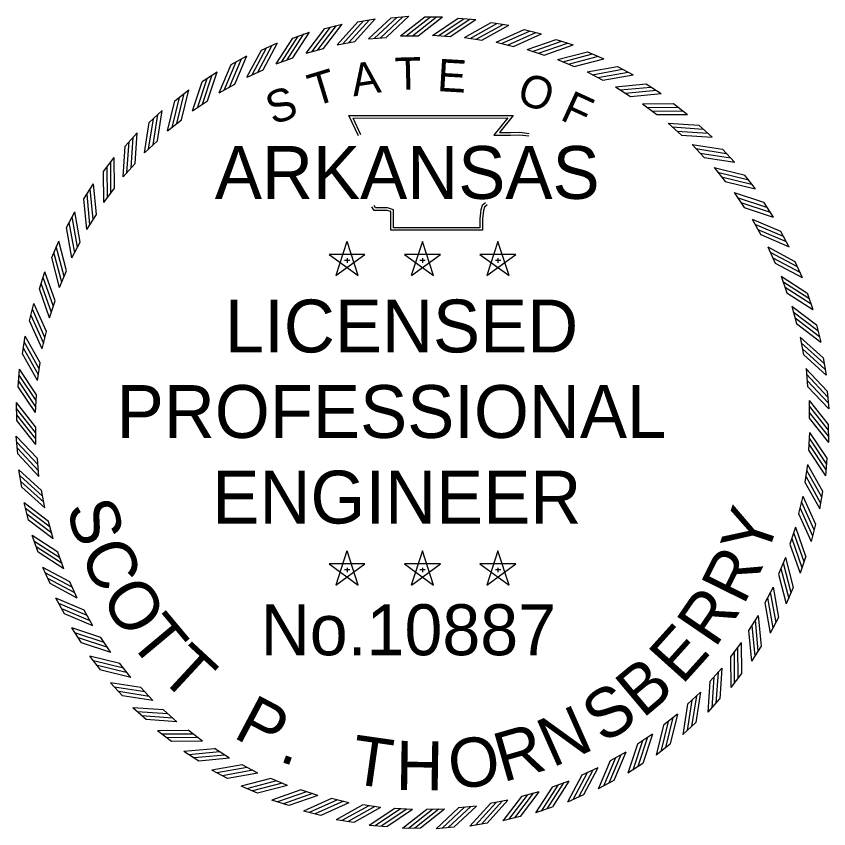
# Model space of a CAD drawing. Extents: x -24122 to 24238, y -8840 to 11381.
# Drawn here: x 3046.5 to 3294.9, y 323.2 to 571.6 of the extents above; entities that cross this region are included whole.
import ezdxf

# ---------------------------------------------------------------- set-up
doc = ezdxf.new("R2010")
doc.units = 0
doc.layers.add('STAMP_PP', color=7, linetype='Continuous')

msp = doc.modelspace()

# ---------------------------------------------------------------- linework, layer by layer
at = {"layer": 'STAMP_PP'}
for p, q in [((3161.08, 571.13), (3166.5, 571.63)), ((3171.39, 571.43), (3176.83, 571.43)), ((3140.85, 567.86), (3146.11, 569.24)), ((3150.9, 569.91), (3156.26, 570.86)), ((3181.58, 571.02), (3187, 570.63)), ((3191.75, 569.7), (3197.12, 568.86)), ((3131.01, 564.98), (3136.14, 566.8)), ((3201.77, 567.55), (3207.06, 566.26)), ((3154.22, 564.68), (3159.65, 565.18)), ((3163.96, 565.64), (3169.41, 565.64)), ((3173.75, 565.8), (3179.19, 565.4)), ((3183.51, 565.14), (3188.9, 564.29)), ((3211.59, 564.57), (3216.75, 562.85)), ((3121.43, 561.3), (3126.4, 563.53)), ((3135.14, 560.37), (3140.42, 561.76)), ((3144.59, 562.92), (3149.96, 563.87)), ((3193.19, 563.68), (3198.49, 562.39)), ((3112.2, 556.85), (3116.96, 559.48)), ((3202.71, 561.42), (3207.89, 559.7)), ((3221.12, 560.8), (3226.13, 558.66)), ((3125.94, 557.05), (3131.08, 558.87)), ((3212.02, 558.39), (3217.03, 556.25)), ((3103.36, 551.64), (3107.89, 554.66)), ((3117.04, 552.98), (3122.01, 555.21)), ((3221.04, 554.6), (3225.86, 552.05)), ((3230.31, 556.24), (3235.12, 553.7)), ((3094.98, 545.72), (3099.24, 549.11)), ((3108.5, 548.19), (3113.27, 550.83)), ((3229.72, 550.08), (3234.32, 547.14)), ((3239.1, 550.95), (3243.68, 548.02)), ((3100.39, 542.71), (3104.93, 545.73)), ((3238, 544.85), (3242.33, 541.54)), ((3247.41, 544.95), (3251.74, 541.64)), ((3087.12, 539.14), (3091.09, 542.86)), ((3092.76, 536.57), (3097.04, 539.96)), ((3245.82, 538.96), (3249.86, 535.3)), ((3255.21, 538.28), (3259.24, 534.63)), ((3079.83, 531.92), (3083.48, 535.96)), ((3085.67, 529.83), (3089.64, 533.56)), ((3253.12, 532.45), (3256.85, 528.47)), ((3262.42, 530.99), (3266.14, 527.02)), ((3073.17, 524.13), (3076.47, 528.45)), ((3079.15, 522.53), (3082.81, 526.58)), ((3259.86, 525.35), (3263.25, 521.08)), ((3269.01, 523.13), (3272.39, 518.87)), ((3067.16, 515.81), (3070.1, 520.39)), ((3073.26, 514.71), (3076.57, 519.05)), ((3265.99, 517.72), (3269.02, 513.18)), ((3274.93, 514.75), (3277.94, 510.23)), ((3061.87, 507.03), (3064.41, 511.84)), ((3068.04, 506.44), (3070.98, 511.03)), ((3271.47, 509.61), (3274.11, 504.84)), ((3280.13, 505.92), (3282.76, 501.15)), ((3057.32, 497.84), (3059.46, 502.84)), ((3063.51, 497.76), (3066.06, 502.58)), ((3147.61, 502.79), (3144.21, 492.34)), ((3151, 492.35), (3147.62, 502.8)), ((3170.69, 502.79), (3167.28, 492.34)), ((3174.08, 492.35), (3170.7, 502.8)), ((3193.77, 502.79), (3190.36, 492.34)), ((3197.16, 492.35), (3193.77, 502.8)), ((3276.26, 501.08), (3278.5, 496.1)), ((3153.1, 498.8), (3142.11, 498.81)), ((3142.12, 498.8), (3151, 492.33)), ((3144.22, 492.35), (3153.11, 498.8)), ((3146.83, 497.04), (3148.46, 497.04)), ((3147.62, 497.63), (3147.62, 496.25)), ((3176.18, 498.8), (3165.19, 498.81)), ((3165.2, 498.8), (3174.08, 492.33)), ((3167.3, 492.35), (3176.19, 498.8)), ((3169.91, 497.04), (3171.54, 497.04)), ((3170.7, 497.63), (3170.7, 496.25)), ((3199.25, 498.8), (3188.27, 498.81)), ((3188.28, 498.8), (3197.16, 492.33)), ((3190.37, 492.35), (3199.27, 498.8)), ((3192.98, 497.04), (3194.62, 497.04)), ((3193.78, 497.63), (3193.78, 496.25)), ((3284.59, 496.68), (3286.82, 491.72)), ((3053.54, 488.3), (3055.26, 493.47)), ((3059.72, 488.74), (3061.86, 493.75)), ((3280.33, 492.18), (3282.15, 487.03)), ((3288.27, 487.11), (3290.08, 481.98)), ((3056.69, 479.43), (3058.41, 484.6)), ((3050.56, 478.49), (3051.85, 483.78)), ((3283.66, 482.97), (3285.04, 477.69)), ((3291.14, 477.26), (3292.53, 472)), ((3054.43, 469.91), (3055.72, 475.2)), ((3048.41, 468.46), (3049.25, 473.84)), ((3286.21, 473.52), (3287.15, 468.15)), ((3293.2, 467.21), (3294.14, 461.86)), ((3052.97, 460.23), (3053.82, 465.61)), ((3047.09, 458.29), (3047.49, 463.72)), ((3287.97, 463.89), (3288.47, 458.46)), ((3052.32, 450.46), (3052.72, 455.9)), ((3294.41, 457.03), (3294.91, 451.61)), ((3046.61, 448.05), (3046.56, 453.49)), ((3288.93, 454.15), (3288.98, 448.7)), ((3052.47, 440.68), (3052.42, 446.13)), ((3294.79, 446.78), (3294.84, 441.34)), ((3046.98, 437.8), (3046.48, 443.22)), ((3289.08, 444.37), (3288.68, 438.93)), ((3053.43, 430.94), (3052.93, 436.37)), ((3294.31, 436.54), (3293.91, 431.11)), ((3048.2, 427.61), (3047.25, 432.97)), ((3288.42, 434.6), (3287.58, 429.21)), ((3055.19, 421.31), (3054.24, 426.68)), ((3286.96, 424.92), (3285.67, 419.62)), ((3292.99, 426.36), (3292.14, 420.99)), ((3050.25, 417.57), (3048.87, 422.83)), ((3057.74, 411.86), (3056.35, 417.13)), ((3284.71, 415.4), (3282.99, 410.22)), ((3290.83, 416.34), (3289.55, 411.05)), ((3053.13, 407.72), (3051.32, 412.85)), ((3061.06, 402.65), (3059.24, 407.79)), ((3147.61, 408.16), (3144.21, 397.72)), ((3151, 397.72), (3147.62, 408.17)), ((3170.69, 408.16), (3167.28, 397.72)), ((3174.08, 397.72), (3170.7, 408.17)), ((3193.77, 408.16), (3190.36, 397.72)), ((3197.16, 397.72), (3193.77, 408.17)), ((3281.68, 406.09), (3279.53, 401.08)), ((3287.86, 406.52), (3286.14, 401.36)), ((3056.81, 398.15), (3054.58, 403.11)), ((3153.1, 404.17), (3142.11, 404.19)), ((3142.12, 404.17), (3151, 397.71)), ((3144.22, 397.72), (3153.11, 404.17)), ((3147.62, 403.01), (3147.62, 401.63)), ((3176.18, 404.17), (3165.19, 404.19)), ((3165.2, 404.17), (3174.08, 397.71)), ((3167.3, 397.72), (3176.19, 404.17)), ((3170.7, 403.01), (3170.7, 401.63)), ((3199.25, 404.17), (3188.27, 404.19)), ((3188.28, 404.17), (3197.16, 397.71)), ((3190.37, 397.72), (3199.27, 404.17)), ((3193.78, 403.01), (3193.78, 401.63)), ((3146.83, 402.42), (3148.46, 402.42)), ((3169.91, 402.42), (3171.54, 402.42)), ((3192.98, 402.42), (3194.62, 402.42)), ((3065.13, 393.75), (3062.9, 398.72)), ((3277.89, 397.07), (3275.33, 392.25)), ((3284.08, 396.99), (3281.94, 391.99)), ((3061.27, 388.91), (3058.63, 393.67)), ((3069.93, 385.22), (3067.29, 389.99)), ((3273.36, 388.39), (3270.42, 383.8)), ((3279.53, 387.8), (3276.98, 382.99)), ((3066.47, 380.07), (3063.45, 384.6)), ((3075.41, 377.11), (3072.38, 381.65)), ((3268.14, 380.11), (3264.83, 375.78)), ((3274.23, 379.01), (3271.3, 374.43)), ((3072.39, 371.7), (3069.01, 375.96)), ((3081.54, 369.48), (3078.15, 373.75)), ((3262.25, 372.3), (3258.59, 368.25)), ((3268.23, 370.7), (3264.93, 366.37)), ((3078.98, 363.84), (3075.25, 367.81)), ((3088.28, 362.38), (3084.55, 366.36)), ((3255.73, 364.99), (3251.75, 361.26)), ((3261.56, 362.91), (3257.92, 358.87)), ((3086.19, 356.55), (3082.15, 360.2)), ((3095.58, 355.87), (3091.54, 359.52)), ((3248.63, 358.25), (3244.36, 354.86)), ((3254.27, 355.69), (3250.31, 351.97)), ((3093.98, 349.88), (3089.66, 353.18)), ((3103.4, 349.98), (3099.06, 353.29)), ((3241, 352.12), (3236.47, 349.1)), ((3246.41, 349.1), (3242.15, 345.72)), ((3102.3, 343.88), (3097.72, 346.81)), ((3111.67, 344.75), (3107.08, 347.69)), ((3232.9, 346.64), (3228.12, 344)), ((3238.04, 343.19), (3233.51, 340.17)), ((3111.08, 338.58), (3106.27, 341.13)), ((3120.35, 340.23), (3115.53, 342.78)), ((3224.36, 341.85), (3219.39, 339.61)), ((3129.38, 336.44), (3124.36, 338.58)), ((3229.2, 337.98), (3224.44, 335.35)), ((3120.27, 334.03), (3115.27, 336.17)), ((3215.46, 337.78), (3210.32, 335.96)), ((3138.68, 333.4), (3133.51, 335.13)), ((3206.25, 334.46), (3200.98, 333.07)), ((3219.96, 333.52), (3215, 331.29)), ((3129.81, 330.26), (3124.65, 331.97)), ((3148.21, 331.15), (3142.91, 332.44)), ((3157.88, 329.69), (3152.5, 330.54)), ((3196.8, 331.91), (3191.43, 330.96)), ((3139.62, 327.28), (3134.34, 328.57)), ((3167.65, 329.03), (3162.21, 329.43)), ((3177.44, 329.18), (3171.98, 329.13)), ((3187.18, 330.14), (3181.75, 329.64)), ((3210.39, 329.84), (3205.26, 328.03)), ((3149.65, 325.12), (3144.28, 325.97)), ((3200.55, 326.97), (3195.28, 325.58)), ((3159.82, 323.8), (3154.39, 324.2)), ((3170.07, 323.33), (3164.62, 323.28)), ((3180.31, 323.7), (3174.9, 323.2)), ((3190.5, 324.91), (3185.14, 323.97))]:
    msp.add_line(p, q, dxfattribs=at)
for points in [[(3157.84, 565.04), (3164.7, 571.48)], [(3159.64, 565.19), (3166.5, 571.63)], [(3163.95, 565.64), (3171.38, 571.43)], [(3165.71, 565.62), (3173.13, 571.41)], [(3167.6, 565.66), (3175.02, 571.45)], [(3169.41, 565.65), (3176.83, 571.44)], [(3140.41, 561.76), (3146.12, 569.25)], [(3144.59, 562.92), (3150.89, 569.91)], [(3146.31, 563.2), (3152.62, 570.19)], [(3148.17, 563.57), (3154.47, 570.56)], [(3149.96, 563.87), (3156.26, 570.86)], [(3154.21, 564.68), (3161.08, 571.12)], [(3155.96, 564.82), (3162.82, 571.27)], [(3173.74, 565.79), (3181.57, 571.02)], [(3175.49, 565.65), (3183.31, 570.88)], [(3177.37, 565.55), (3185.2, 570.78)], [(3179.18, 565.4), (3187.01, 570.63)], [(3183.51, 565.14), (3191.74, 569.7)], [(3185.23, 564.85), (3193.47, 569.41)], [(3187.11, 564.59), (3195.34, 569.16)], [(3131.07, 558.87), (3136.14, 566.8)], [(3135.14, 560.36), (3140.84, 567.85)], [(3136.84, 560.79), (3142.54, 568.28)], [(3138.65, 561.32), (3144.36, 568.8)], [(3188.89, 564.3), (3197.13, 568.86)], [(3193.18, 563.68), (3201.77, 567.55)], [(3194.88, 563.25), (3203.46, 567.12)], [(3196.73, 562.84), (3205.31, 566.71)], [(3125.93, 557.04), (3131, 564.98)], [(3127.59, 557.61), (3132.66, 565.54)], [(3129.36, 558.28), (3134.42, 566.21)], [(3198.48, 562.39), (3207.07, 566.26)], [(3202.71, 561.42), (3211.58, 564.57)], [(3204.36, 560.85), (3213.24, 564)], [(3118.64, 553.67), (3123.03, 562)], [(3120.34, 554.49), (3124.74, 562.81)], [(3122, 555.22), (3126.4, 563.54)], [(3206.17, 560.3), (3215.04, 563.44)], [(3207.88, 559.71), (3216.76, 562.85)], [(3113.27, 550.83), (3116.96, 559.49)], [(3117.03, 552.97), (3121.43, 561.3)], [(3212.01, 558.39), (3221.11, 560.79)], [(3213.62, 557.69), (3222.72, 560.09)], [(3215.37, 556.98), (3224.47, 559.39)], [(3108.5, 548.18), (3112.19, 556.84)], [(3110.04, 549.01), (3113.73, 557.67)], [(3111.67, 549.96), (3115.37, 558.62)], [(3217.03, 556.25), (3226.13, 558.66)], [(3104.92, 545.73), (3107.89, 554.67)], [(3221.04, 554.6), (3230.31, 556.24)], [(3222.58, 553.77), (3231.85, 555.41)], [(3224.27, 552.92), (3233.54, 554.56)], [(3100.39, 542.7), (3103.36, 551.63)], [(3101.86, 543.66), (3104.82, 552.59)], [(3103.41, 544.74), (3106.37, 553.67)], [(3225.86, 552.06), (3235.13, 553.7)], [(3097.03, 539.96), (3099.25, 549.11)], [(3229.71, 550.08), (3239.09, 550.95)], [(3231.18, 549.12), (3240.55, 549.99)], [(3094.14, 537.64), (3096.36, 546.79)], [(3095.6, 538.85), (3097.82, 548)], [(3232.8, 548.13), (3242.17, 549.01)], [(3234.31, 547.14), (3243.69, 548.02)], [(3092.76, 536.57), (3094.98, 545.72)], [(3237.99, 544.85), (3247.4, 544.95)], [(3088.3, 532.34), (3089.76, 541.64)], [(3089.64, 533.56), (3091.09, 542.86)], [(3239.37, 543.78), (3248.79, 543.87)], [(3240.9, 542.66), (3250.31, 542.76)], [(3242.33, 541.55), (3251.74, 541.64)], [(3085.67, 529.83), (3087.12, 539.13)], [(3086.95, 531.01), (3088.41, 540.31)], [(3151.11, 535.02), (3148.21, 541.3), (3198.39, 541.33), (3194.2, 536.06), (3197.61, 536.11), (3200.46, 536.14), (3203.3, 535.83)], [(3151.84, 535.35), (3149.46, 540.5), (3196.74, 540.53), (3192.54, 535.24), (3197.62, 535.31), (3200.42, 535.35), (3203.22, 535.04)], [(3245.81, 538.96), (3255.2, 538.28)], [(3247.1, 537.78), (3256.49, 537.09)], [(3081.57, 525.24), (3082.25, 534.63)], [(3082.8, 526.57), (3083.48, 535.96)], [(3248.53, 536.54), (3257.92, 535.86)], [(3249.86, 535.31), (3259.25, 534.63)], [(3079.15, 522.52), (3079.83, 531.91)], [(3080.34, 523.81), (3081.02, 533.2)], [(3253.11, 532.45), (3262.41, 530.99)], [(3254.3, 531.16), (3263.6, 529.7)], [(3255.62, 529.81), (3264.92, 528.35)], [(3075.45, 517.62), (3075.35, 527.03)], [(3076.56, 519.05), (3076.47, 528.46)], [(3256.85, 528.47), (3266.15, 527.02)], [(3074.34, 516.09), (3074.24, 525.5)], [(3259.85, 525.35), (3269, 523.13)], [(3073.26, 514.71), (3073.16, 524.12)], [(3260.93, 523.97), (3270.08, 521.75)], [(3262.13, 522.51), (3271.28, 520.3)], [(3070.97, 511.03), (3070.1, 520.4)], [(3263.25, 521.08), (3272.4, 518.87)], [(3068.99, 507.9), (3068.12, 517.27)], [(3069.98, 509.51), (3069.1, 518.88)], [(3265.98, 517.72), (3274.92, 514.76)], [(3068.04, 506.43), (3067.16, 515.8)], [(3189.98, 514.61), (3188.93, 513.75), (3188.56, 512.4), (3188.27, 509.7), (3188.27, 506.98), (3161.85, 506.98), (3161.85, 510.87), (3161.85, 512.49), (3160.03, 513.05), (3156.36, 513.05), (3155.89, 513.77)], [(3266.94, 516.26), (3275.88, 513.29)], [(3268.02, 514.71), (3276.96, 511.74)], [(3066.06, 502.57), (3064.41, 511.84)], [(3190.49, 513.99), (3189.63, 513.29), (3189.35, 512.25), (3189.06, 509.65), (3189.06, 506.18), (3161.05, 506.18), (3161.05, 510.87), (3161.05, 511.91), (3159.91, 512.25), (3155.93, 512.25), (3155.22, 513.33)], [(3269.02, 513.19), (3277.95, 510.22)], [(3065.19, 500.98), (3063.55, 510.25)], [(3271.46, 509.61), (3280.12, 505.92)], [(3063.51, 497.75), (3061.87, 507.02)], [(3064.35, 499.29), (3062.7, 508.56)], [(3272.3, 508.07), (3280.96, 504.38)], [(3273.25, 506.44), (3281.91, 502.75)], [(3274.11, 504.85), (3282.77, 501.15)], [(3061.86, 493.75), (3059.46, 502.85)], [(3060.43, 490.33), (3058.02, 499.43)], [(3061.13, 492.09), (3058.73, 501.19)], [(3276.26, 501.08), (3284.58, 496.68)], [(3276.96, 499.48), (3285.28, 495.08)], [(3059.72, 488.73), (3057.32, 497.83)], [(3277.77, 497.77), (3286.1, 493.37)], [(3278.5, 496.11), (3286.83, 491.71)], [(3058.4, 484.6), (3055.26, 493.47)], [(3280.33, 492.18), (3288.26, 487.11)], [(3057.26, 481.08), (3054.11, 489.95)], [(3057.82, 482.88), (3054.67, 491.76)], [(3280.9, 490.52), (3288.83, 485.46)], [(3056.69, 479.42), (3053.54, 488.29)], [(3281.57, 488.76), (3289.5, 483.69)], [(3282.15, 487.04), (3290.09, 481.97)], [(3055.27, 473.44), (3051.4, 482.02)], [(3055.72, 475.2), (3051.85, 483.78)], [(3283.65, 482.97), (3291.14, 477.27)], [(3054.87, 471.6), (3051, 480.18)], [(3284.08, 481.28), (3291.57, 475.57)], [(3054.44, 469.9), (3050.57, 478.48)], [(3284.6, 479.46), (3292.09, 473.75)], [(3285.05, 477.7), (3292.53, 472)], [(3053.52, 463.82), (3048.95, 472.05)], [(3053.82, 465.61), (3049.25, 473.84)], [(3286.2, 473.53), (3293.19, 467.22)], [(3053.26, 461.95), (3048.7, 470.18)], [(3286.49, 471.8), (3293.48, 465.49)], [(3286.86, 469.94), (3293.85, 463.64)], [(3052.98, 460.22), (3048.41, 468.45)], [(3287.16, 468.16), (3294.15, 461.85)], [(3052.71, 455.89), (3047.48, 463.72)], [(3287.96, 463.9), (3294.41, 457.04)], [(3288.11, 462.15), (3294.55, 455.29)], [(3052.47, 452.2), (3047.24, 460.03)], [(3052.56, 454.09), (3047.33, 461.92)], [(3288.32, 460.27), (3294.77, 453.41)], [(3052.32, 450.46), (3047.09, 458.28)], [(3288.47, 458.47), (3294.92, 451.61)], [(3052.41, 446.12), (3046.56, 453.49)], [(3288.92, 454.16), (3294.78, 446.79)], [(3288.92, 452.41), (3294.78, 445.04)], [(3052.41, 444.31), (3046.56, 451.68)], [(3052.47, 442.42), (3046.62, 449.79)], [(3288.98, 450.52), (3294.84, 443.15)], [(3052.47, 440.67), (3046.62, 448.04)], [(3288.98, 448.7), (3294.84, 441.33)], [(3052.93, 436.36), (3046.48, 443.22)], [(3288.93, 442.63), (3294.16, 434.8)], [(3289.08, 444.37), (3294.31, 436.54)], [(3053.08, 434.55), (3046.63, 441.41)], [(3288.83, 440.74), (3294.06, 432.91)], [(3053.29, 432.67), (3046.84, 439.54)], [(3053.43, 430.93), (3046.99, 437.79)], [(3288.68, 438.93), (3293.91, 431.1)], [(3054.24, 426.67), (3047.25, 432.98)], [(3288.13, 432.88), (3292.7, 424.65)], [(3288.42, 434.61), (3292.99, 426.37)], [(3054.54, 424.88), (3047.55, 431.19)], [(3287.88, 431.01), (3292.44, 422.77)], [(3054.91, 423.03), (3047.92, 429.33)], [(3055.2, 421.3), (3048.21, 427.61)], [(3287.58, 429.22), (3292.15, 420.98)], [(3286.96, 424.93), (3290.83, 416.35)], [(3056.35, 417.13), (3048.86, 422.83)], [(3286.53, 423.23), (3290.4, 414.65)], [(3056.8, 415.37), (3049.31, 421.07)], [(3286.12, 421.39), (3289.99, 412.8)], [(3057.32, 413.55), (3049.83, 419.26)], [(3057.75, 411.85), (3050.26, 417.56)], [(3285.68, 419.63), (3289.55, 411.05)], [(3284.71, 415.41), (3287.85, 406.53)], [(3059.24, 407.79), (3051.31, 412.85)], [(3284.14, 413.75), (3287.29, 404.88)], [(3059.83, 406.07), (3051.9, 411.14)], [(3282.99, 410.23), (3286.14, 401.36)], [(3283.58, 411.94), (3286.73, 403.07)], [(3060.5, 404.3), (3052.57, 409.37)], [(3061.07, 402.65), (3053.14, 407.72)], [(3281.67, 406.1), (3284.08, 397)], [(3062.9, 398.72), (3054.57, 403.11)], [(3280.27, 402.74), (3282.67, 393.64)], [(3280.97, 404.5), (3283.37, 395.39)], [(3063.62, 397.06), (3055.3, 401.45)], [(3279.54, 401.08), (3281.94, 391.98)], [(3064.44, 395.35), (3056.11, 399.75)], [(3065.14, 393.75), (3056.82, 398.14)], [(3277.05, 395.54), (3278.69, 386.27)], [(3277.88, 397.08), (3279.53, 387.81)], [(3067.29, 389.98), (3058.63, 393.67)], [(3276.2, 393.85), (3277.85, 384.58)], [(3068.15, 388.39), (3059.49, 392.08)], [(3069.1, 386.75), (3060.44, 390.45)], [(3275.34, 392.25), (3276.98, 382.98)], [(3069.93, 385.21), (3061.27, 388.91)], [(3273.36, 388.4), (3274.23, 379.02)], [(3271.42, 385.32), (3272.29, 375.94)], [(3272.4, 386.93), (3273.28, 377.56)], [(3072.38, 381.64), (3063.45, 384.6)], [(3073.37, 380.12), (3064.44, 383.09)], [(3270.43, 383.8), (3271.3, 374.43)], [(3074.46, 378.57), (3065.52, 381.54)], [(3268.14, 380.12), (3268.23, 370.71)], [(3075.41, 377.1), (3066.48, 380.07)], [(3267.06, 378.74), (3267.16, 369.33)], [(3078.15, 373.74), (3069, 375.96)], [(3264.83, 375.78), (3264.93, 366.37)], [(3265.95, 377.21), (3266.04, 367.8)], [(3079.26, 372.31), (3070.11, 374.53)], [(3080.47, 370.86), (3071.32, 373.08)], [(3081.55, 369.48), (3072.4, 371.69)], [(3261.06, 371.02), (3260.38, 361.63)], [(3262.25, 372.3), (3261.57, 362.91)], [(3084.55, 366.35), (3075.25, 367.81)], [(3258.6, 368.25), (3257.92, 358.86)], [(3259.82, 369.59), (3259.14, 360.2)], [(3085.78, 365.02), (3076.48, 366.47)], [(3087.1, 363.67), (3077.8, 365.12)], [(3088.29, 362.38), (3078.98, 363.84)], [(3254.44, 363.81), (3252.99, 354.51)], [(3255.73, 365), (3254.28, 355.7)], [(3251.76, 361.26), (3250.3, 351.96)], [(3253.09, 362.49), (3251.64, 353.19)], [(3091.54, 359.52), (3082.15, 360.2)], [(3092.87, 358.29), (3083.48, 358.97)], [(3248.64, 358.26), (3246.42, 349.11)], [(3094.3, 357.05), (3084.91, 357.73)], [(3095.59, 355.87), (3086.2, 356.55)], [(3245.8, 355.98), (3243.58, 346.83)], [(3247.25, 357.18), (3245.04, 348.04)], [(3099.07, 353.28), (3089.65, 353.18)], [(3244.37, 354.86), (3242.15, 345.72)], [(3100.5, 352.16), (3091.08, 352.07)], [(3102.02, 351.05), (3092.61, 350.96)], [(3239.54, 351.17), (3236.58, 342.24)], [(3241.01, 352.13), (3238.04, 343.19)], [(3103.41, 349.98), (3093.99, 349.88)], [(3236.47, 349.1), (3233.51, 340.16)], [(3237.99, 350.09), (3235.03, 341.15)], [(3107.08, 347.68), (3097.71, 346.81)], [(3108.6, 346.69), (3099.23, 345.82)], [(3110.22, 345.71), (3100.84, 344.84)], [(3231.36, 345.81), (3227.66, 337.16)], [(3232.9, 346.65), (3229.2, 337.99)], [(3111.68, 344.75), (3102.31, 343.88)], [(3228.13, 344), (3224.44, 335.34)], [(3229.72, 344.86), (3226.03, 336.2)], [(3115.54, 342.77), (3106.27, 341.13)], [(3117.13, 341.91), (3107.86, 340.27)], [(3118.82, 341.06), (3109.55, 339.42)], [(3222.76, 341.15), (3218.37, 332.83)], [(3224.36, 341.86), (3219.97, 333.53)], [(3120.36, 340.23), (3111.09, 338.58)], [(3124.37, 338.57), (3115.26, 336.17)], [(3219.39, 339.61), (3215, 331.29)], [(3221.05, 340.34), (3216.66, 332.01)], [(3126.03, 337.85), (3116.92, 335.44)], [(3127.78, 337.14), (3118.68, 334.74)], [(3129.38, 336.44), (3120.28, 334.03)], [(3210.33, 335.96), (3205.26, 328.02)], [(3212.04, 336.55), (3206.97, 328.61)], [(3213.81, 337.22), (3208.74, 329.28)], [(3215.46, 337.78), (3210.4, 329.85)], [(3133.51, 335.12), (3124.64, 331.97)], [(3135.23, 334.53), (3126.35, 331.38)], [(3137.03, 333.97), (3128.16, 330.83)], [(3138.69, 333.41), (3129.82, 330.26)], [(3200.99, 333.07), (3195.28, 325.58)], [(3202.74, 333.51), (3197.04, 326.02)], [(3204.56, 334.03), (3198.85, 326.54)], [(3206.26, 334.46), (3200.55, 326.97)], [(3142.91, 332.43), (3134.33, 328.56)], [(3144.67, 331.99), (3136.09, 328.12)], [(3146.52, 331.58), (3137.93, 327.71)], [(3148.21, 331.15), (3139.63, 327.28)], [(3152.5, 330.53), (3144.27, 325.97)], [(3191.44, 330.96), (3185.14, 323.96)], [(3193.23, 331.25), (3186.92, 324.26)], [(3195.08, 331.62), (3188.78, 324.63)], [(3196.81, 331.91), (3190.5, 324.92)], [(3154.29, 330.23), (3146.06, 325.67)], [(3156.16, 329.98), (3147.93, 325.42)], [(3157.89, 329.69), (3149.66, 325.13)], [(3162.22, 329.43), (3154.39, 324.2)], [(3164.02, 329.28), (3156.2, 324.05)], [(3165.91, 329.18), (3158.08, 323.95)], [(3167.66, 329.04), (3159.83, 323.81)], [(3171.99, 329.13), (3164.62, 323.27)], [(3173.8, 329.13), (3166.43, 323.27)], [(3175.69, 329.19), (3168.32, 323.33)], [(3177.44, 329.19), (3170.07, 323.33)], [(3181.75, 329.64), (3174.89, 323.19)], [(3183.56, 329.79), (3176.7, 323.34)], [(3185.44, 330.01), (3178.58, 323.56)], [(3187.18, 330.15), (3180.32, 323.7)]]:
    msp.add_lwpolyline(points, dxfattribs=at)

# ---------------------------------------------------------------- texts
for s, height, rotation, p in [('T', 9.9, 1.4789, (3162.37, 549.07)), ('A', 9.9, 8.6788, (3149.58, 547.1)), ('E', 9.9, 356.672, (3175.03, 548.77)), ('T', 9.9, 16.9015, (3137.57, 543.96)), ('O', 9.9, 341.2218, (3199.07, 545.37)), ('S', 9.9, 19.7726, (3124.98, 538.31)), ('F', 9.9, 335.3628, (3212.41, 540.16)), ('S', 15.03, 286.9475, (3061.59, 421.47)), ('Y', 15.03, 71.7733, (3275.78, 405.43)), ('C', 15.03, 294.2435, (3065.77, 407.76)), ('R', 15.03, 63.7477, (3268.9, 391.25)), ('O', 15.03, 301.9044, (3071.99, 394.05)), ('R', 15.03, 55.7221, (3260.1, 378.16)), ('T', 15.03, 309.93, (3080.41, 380.72)), ('E', 15.03, 48.0613, (3250.08, 366.93)), ('T', 15.03, 317.226, (3089.62, 369.73)), ('B', 15.03, 40.0357, (3238.07, 356.71)), ('S', 15.03, 32.7397, (3226.01, 348.95)), ('P', 15.03, 332.1828, (3112.43, 351.3)), ('N', 15.03, 23.9845, (3210.39, 341.76)), ('R', 15.03, 15.9589, (3195.26, 337.33)), ('T', 15.03, 351.882, (3148.26, 337.1)), ('O', 15.03, 7.9332, (3179.65, 335.05)), ('H', 15.03, 359.178, (3162.46, 335.08)), ('.', 15.03, 340.2084, (3126.42, 344.03))]:
    msp.add_text(s, height=height, rotation=rotation, dxfattribs=at).set_placement(p)
for s, height, p in [('ARKANSAS', 16.155, (3107.2, 515.79)), ('LICENSED', 16.155, (3110.27, 468.84)), ('PROFESSIONAL', 16.1547, (3077.19, 442.69)), ('ENGINEER', 16.155, (3106.43, 416.53)), ('No.10887', 15.578, (3121.19, 376.25))]:
    msp.add_text(s, height=height, dxfattribs=at).set_placement(p)

doc.saveas('drawing.dxf')
